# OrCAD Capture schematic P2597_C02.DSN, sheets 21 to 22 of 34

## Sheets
21 13_Gigabit Ethernet: size Custom
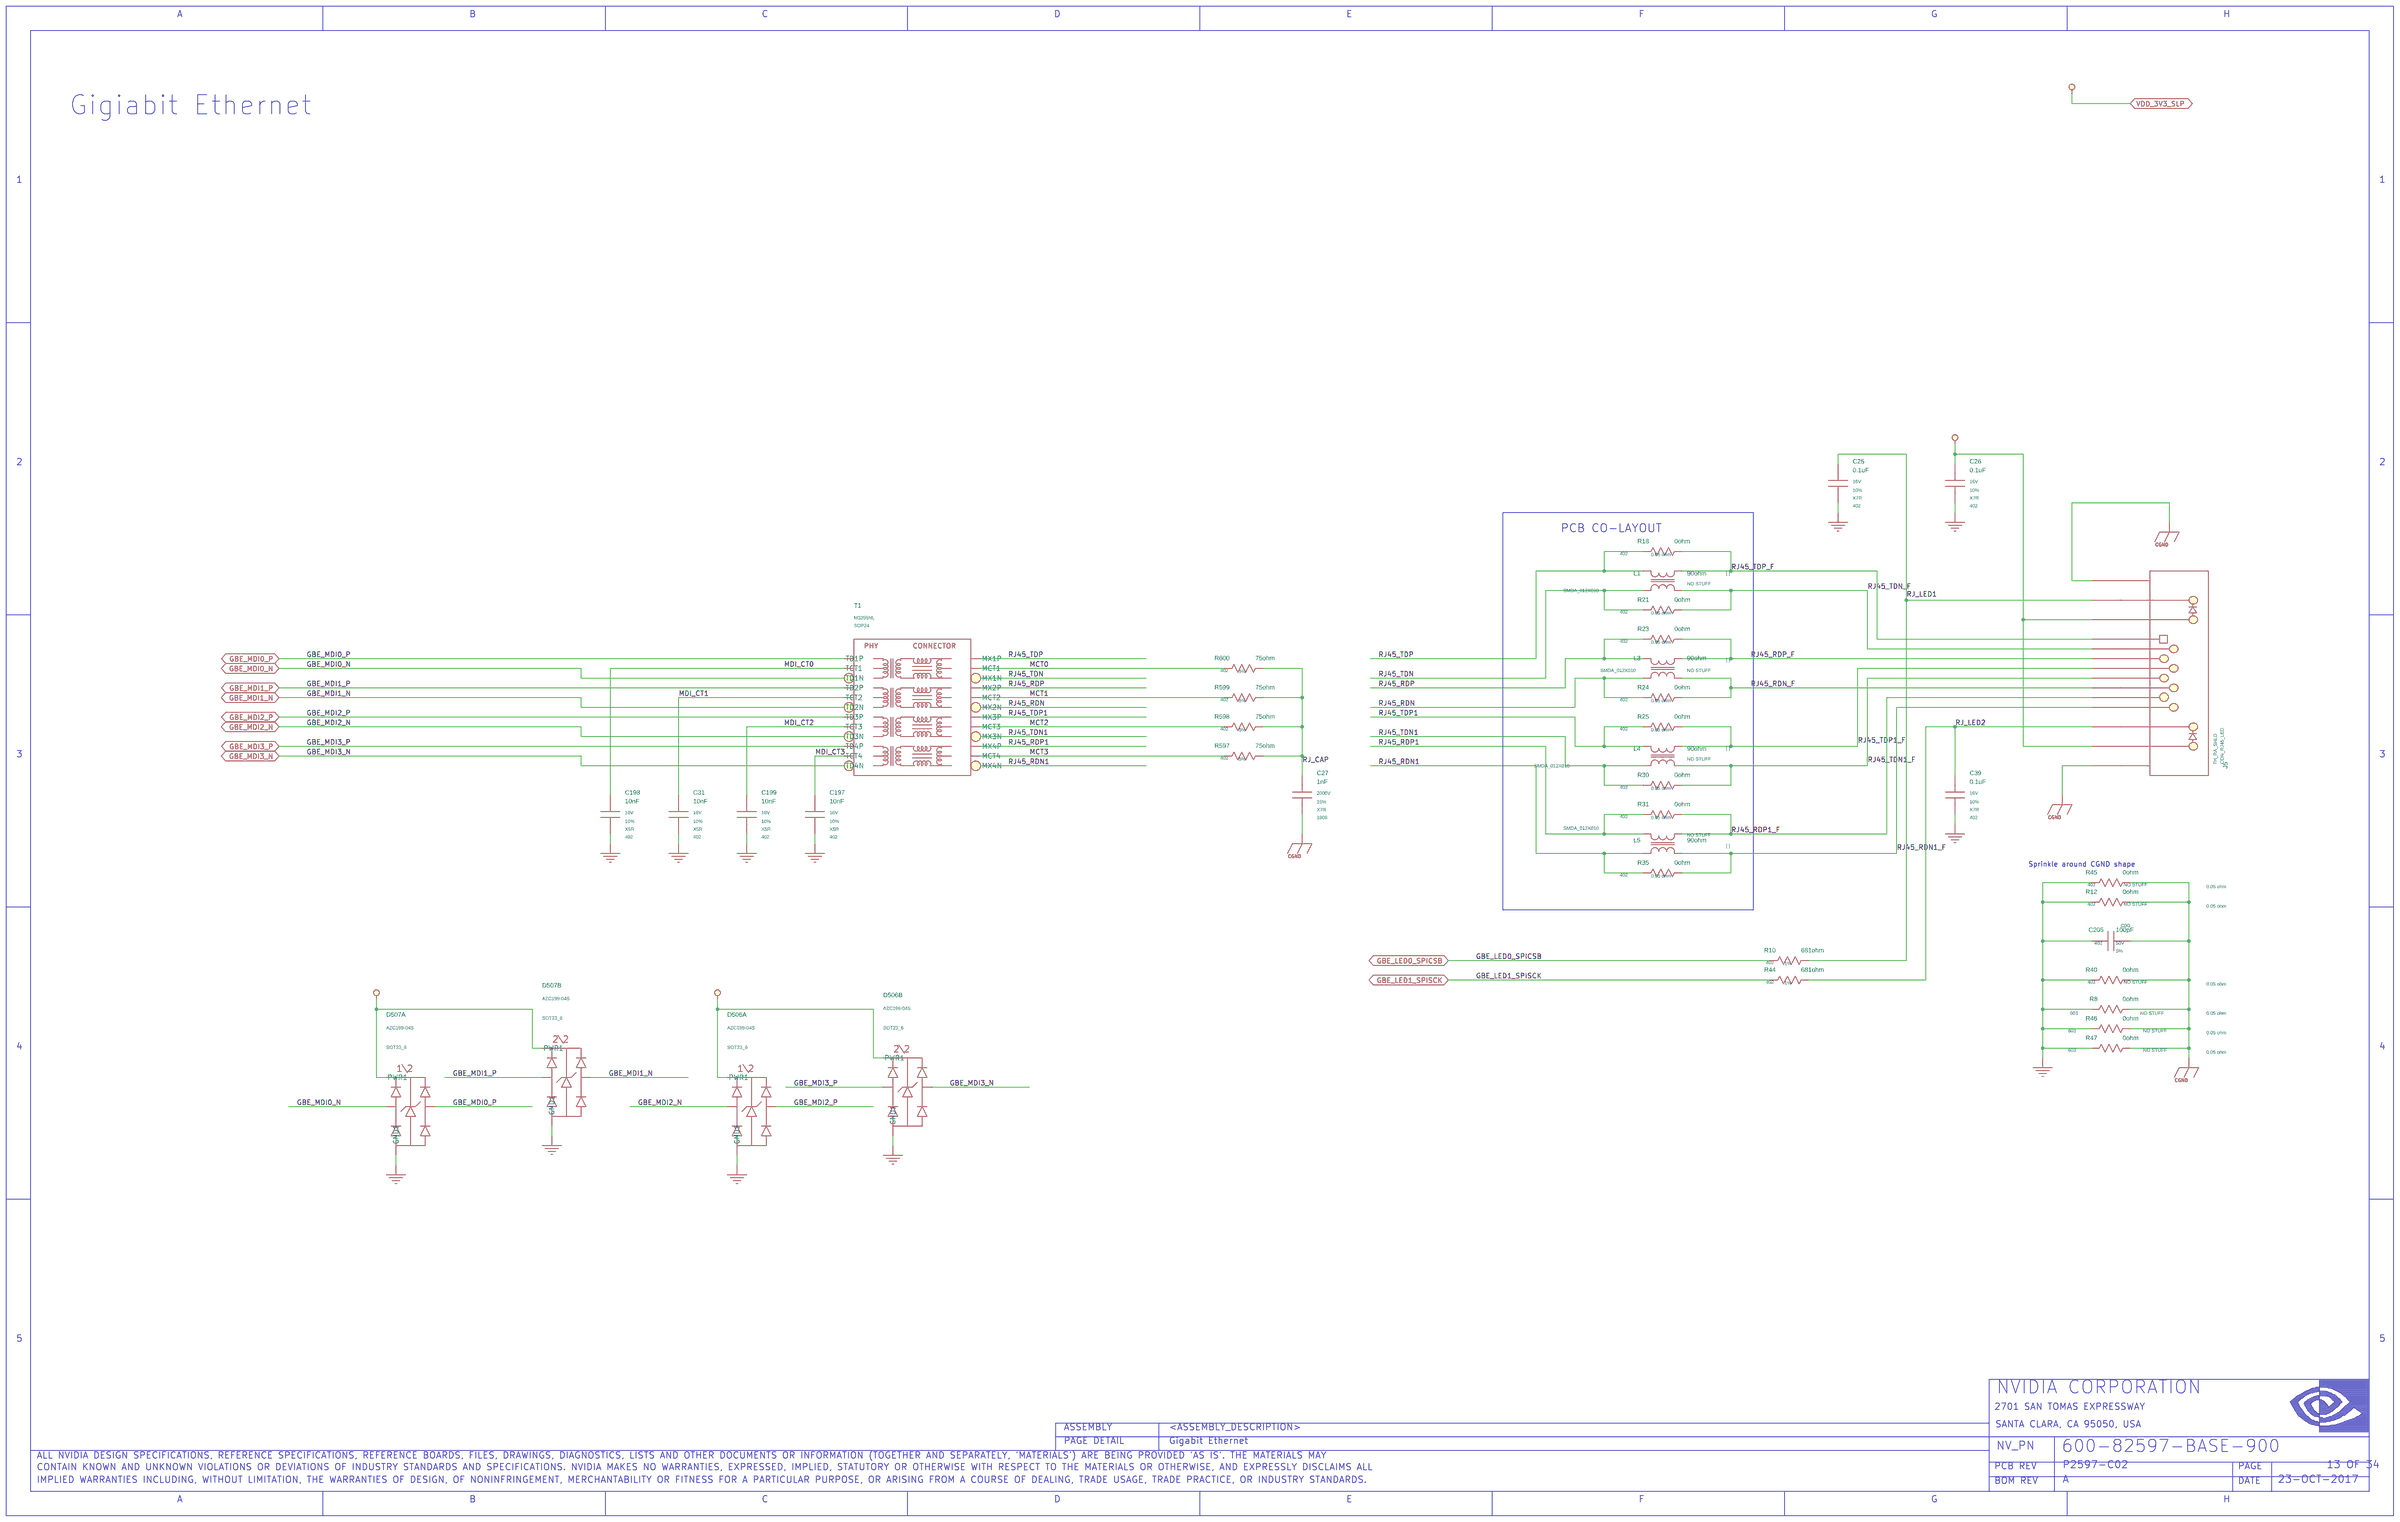
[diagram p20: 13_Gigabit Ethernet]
22 12_SATA: size Custom
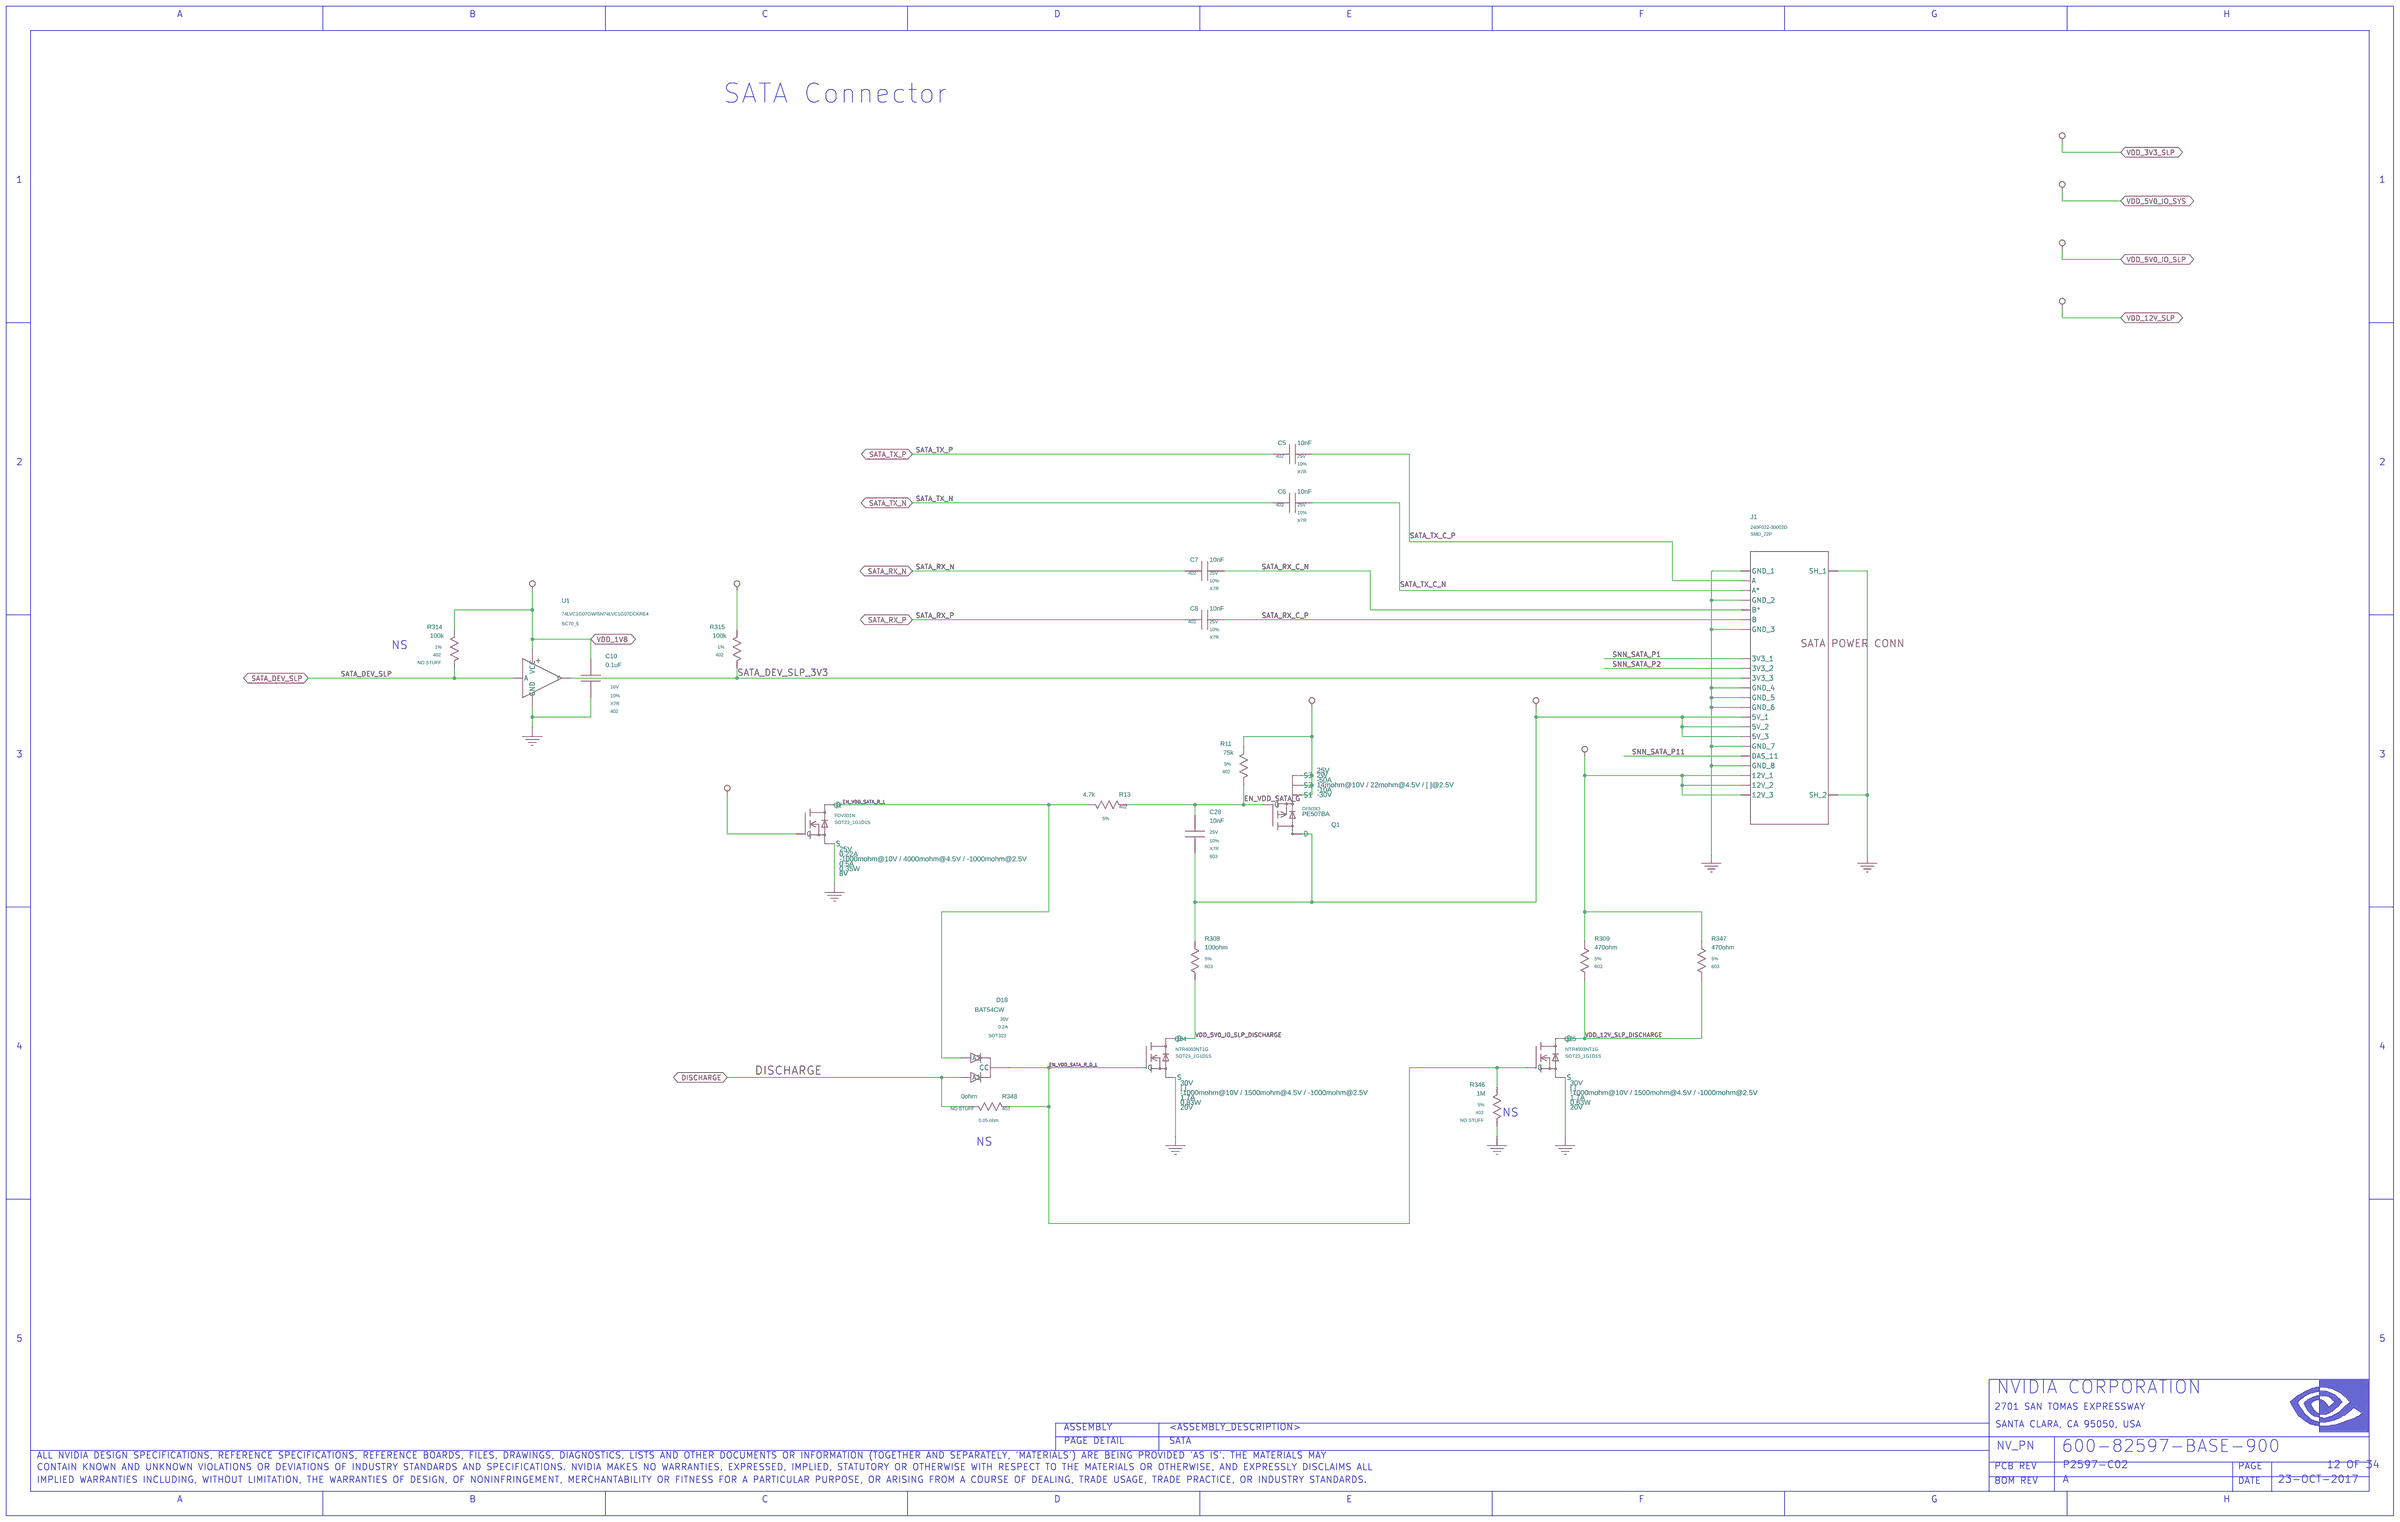
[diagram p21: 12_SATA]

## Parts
sheet 12_SATA
C5  10nF  [402]
C6  10nF  [402]
C7  10nF  [402]
C8  10nF  [402]
C10  0.1uF  [402]
C28  10nF  [603]
D18  D_3PIN_CC  [SOT323]
J1  CON_SATA  [CON_SATA_022_SMT_RA_F_P013_C]
Q1  Q_FET_P_ENH  [DFET_SMD_032X033]
Q2  Q_FET_N_ENH  [SOT23]
Q34  Q_FET_N_ENH  [SOT23]
Q35  Q_FET_N_ENH  [SOT23]
R11  75k  [402]
R13  4.7k  [402]
R308  100ohm  [603]
R309  470ohm  [603]
R314  100k  [402]
R315  100k  [402]
R346  1M  [402]
R347  470ohm  [603]
R348  0ohm  [402]
U1  U_BUF_OD  [SC70_5]
sheet 13_Gigabit Ethernet
C25  0.1uF  [402]
C26  0.1uF  [402]
C27  1nF  [4520MM]
C31  10nF  [402]
C39  0.1uF  [402]
C197  10nF  [402]
C198  10nF  [402]
C199  10nF  [402]
C205  100pF  [402]
D506  D_ESD_DIFFPAIR  [SOT23_6]  (sections A,B)
D507  D_ESD_DIFFPAIR  [SOT23_6]  (sections A,B)
J5  CON_RJ45  [CON_MJ08_012_TH_RA_2LED]
L1  90ohm  [IND_NONRKO_SMD_012X010]
L3  90ohm  [IND_NONRKO_SMD_012X010]
L4  90ohm  [IND_NONRKO_SMD_012X010]
L5  90ohm  [IND_NONRKO_SMD_012X010]
R8  0ohm  [603]
R10  681ohm  [402]
R12  0ohm  [402]
R18  0ohm  [402]
R21  0ohm  [402]
R23  0ohm  [402]
R24  0ohm  [402]
R25  0ohm  [402]
R30  0ohm  [402]
R31  0ohm  [402]
R35  0ohm  [402]
R40  0ohm  [402]
R44  681ohm  [402]
R45  0ohm  [402]
R46  0ohm  [603]
R47  0ohm  [603]
R597  75ohm  [402]
R598  75ohm  [402]
R599  75ohm  [402]
R600  75ohm  [402]
T1  1:01  [XFMR_SMD_24_151X071]

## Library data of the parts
C5 = C#1: ASSEMBLY: SATA; CDS_LIB: discrete; CDS_PART_NAME: C_0402-10NF,X7R,10%,25V,036-0019-000; CDS_PHYS_PART_NAME: C_0402-10NF,X7R,10%,25V,036-0019-000-036-0019-000,10NF; CDS_SEC: 1; CHIPS_PART_NAME: C; DEVICE_TYPENAME: C_0402-10NFX7R1025V036-0019-000-036-0019-00010NF; DRAWING: @P2597_C02_LIB.P2597_C02(SCH_1):PAGE12; MAT: X7R; MAX_VOLTAGE: 25V; NV_PN: 036-0019-000; PATH: I28; PHYS_PAGE: 12; ROT: 0; SEC: 1; SIGNAL_MODEL: nv_cap; TOL: 10%; VER: 2; XY: (-5550,5300)
C6 = C#1: ASSEMBLY: SATA; CDS_LIB: discrete; CDS_PART_NAME: C_0402-10NF,X7R,10%,25V,036-0019-000; CDS_PHYS_PART_NAME: C_0402-10NF,X7R,10%,25V,036-0019-000-036-0019-000,10NF; CDS_SEC: 1; CHIPS_PART_NAME: C; DEVICE_TYPENAME: C_0402-10NFX7R1025V036-0019-000-036-0019-00010NF; DRAWING: @P2597_C02_LIB.P2597_C02(SCH_1):PAGE12; MAT: X7R; MAX_VOLTAGE: 25V; NV_PN: 036-0019-000; PATH: I29; PHYS_PAGE: 12; ROT: 0; SEC: 1; SIGNAL_MODEL: nv_cap; TOL: 10%; VER: 2; XY: (-5550,5050)
C7 = C#1: ASSEMBLY: SATA; CDS_LIB: discrete; CDS_PART_NAME: C_0402-10NF,X7R,10%,25V,036-0019-000; CDS_PHYS_PART_NAME: C_0402-10NF,X7R,10%,25V,036-0019-000-036-0019-000,10NF; CDS_SEC: 1; CHIPS_PART_NAME: C; DEVICE_TYPENAME: C_0402-10NFX7R1025V036-0019-000-036-0019-00010NF; DRAWING: @P2597_C02_LIB.P2597_C02(SCH_1):PAGE12; MAT: X7R; MAX_VOLTAGE: 25V; NV_PN: 036-0019-000; PATH: I26; PHYS_PAGE: 12; ROT: 0; SEC: 1; SIGNAL_MODEL: nv_cap; TOL: 10%; VER: 2; XY: (-6000,4700)
C8 = C#1: ASSEMBLY: SATA; CDS_LIB: discrete; CDS_PART_NAME: C_0402-10NF,X7R,10%,25V,036-0019-000; CDS_PHYS_PART_NAME: C_0402-10NF,X7R,10%,25V,036-0019-000-036-0019-000,10NF; CDS_SEC: 1; CHIPS_PART_NAME: C; DEVICE_TYPENAME: C_0402-10NFX7R1025V036-0019-000-036-0019-00010NF; DRAWING: @P2597_C02_LIB.P2597_C02(SCH_1):PAGE12; MAT: X7R; MAX_VOLTAGE: 25V; NV_PN: 036-0019-000; PATH: I27; PHYS_PAGE: 12; ROT: 0; SEC: 1; SIGNAL_MODEL: nv_cap; TOL: 10%; VER: 2; XY: (-6000,4450)
C10 = C: ASSEMBLY: SATA; CDS_LIB: discrete; CDS_PART_NAME: C_0402-0.1UF,X7R,10%,16V,036-0014-000; CDS_PHYS_PART_NAME: C_0402-0.1UF,X7R,10%,16V,036-0014-000-0.1UF,036-0014-000; CDS_SEC: 1; DEVICE_TYPENAME: C_0402-01UFX7R1016V036-0014-000-01UF036-0014-000; DRAWING: @P2597_C02_LIB.P2597_C02(SCH_1):PAGE12; MAT: X7R; MAX_VOLTAGE: 16V; NV_PN: 036-0014-000; PATH: I54; PHYS_PAGE: 12; ROT: 0; SEC: 1; SIGNAL_MODEL: nv_cap; TOL: 10%; VER: 1; XY: (-9150,4150)
C28 = C: ASSEMBLY: SATA; CDS_LIB: discrete; CDS_PART_NAME: C_0603-10NF,X7R,10%,25V,036-0042-000; CDS_PHYS_PART_NAME: C_0603-10NF,X7R,10%,25V,036-0042-000-036-0042-000,10NF; CDS_SEC: 1; DEVICE_TYPENAME: C_0603-10NFX7R1025V036-0042-000-036-0042-00010NF; DRAWING: @P2597_C02_LIB.P2597_C02(SCH_1):PAGE12; MAT: X7R; MAX_VOLTAGE: 25V; NV_PN: 036-0042-000; PATH: I39; PHYS_PAGE: 12; ROT: 0; SEC: 1; SIGNAL_MODEL: nv_cap; TOL: 10%; VER: 1; XY: (-6050,3350)
D18 = D_3PIN_CC: ASSEMBLY: PWR_DIS; CDS_LIB: discrete; CDS_PART_NAME: D_3PIN_CC_SOT323-BAT54CW,1 PAIR - COMMON CATHODE,30V,0.6A,1V@0.1A,0.2A,091-0022-000; CDS_PHYS_PART_NAME: D_3PIN_CC_SOT323-BAT54CW,1 PAIR - COMMON CATHODE,30V,0.6A,1V@0.1A,0.2A,091-0022-000-091-0022-000; CDS_SEC: 1; CONFIGURATION: 1 Pair - Common Cathode; CONTINUOUS_CURRENT: 0.2A; DEVICE_TYPENAME: D_3PIN_CC_SOT323-BAT54CW1PAIR-COMMONCATHODE30V06A1V01A02A091-0022-000-091-0022-000; DRAWING: @P2597_C02_LIB.P2597_C02(SCH_1):PAGE12; FORWARD_VOLTAGE: 1V@0.1A; MAX_CURRENT: 0.6A; MAX_VOLTAGE: 30V; NV_NAME: BAT54CW; NV_PN: 091-0022-000; PATH: I83; PHYS_PAGE: 12; ROT: 2; SEC: 1; VER: 1; XY: (-7100,2150)
J1 = CON_SATA: ANGLE: 90; ASSEMBLY: SATA; CDS_LIB: electro_mechanic; CDS_PART_NAME: CON_SATA_SMD_22P-240F022-30002D,FEMALE,1.27MM,90,YES,N/A,YES,NO,N/A,N/A,N/A,080-0599-000; CDS_PHYS_PART_NAME: CON_SATA_SMD_22P-240F022-30002D,FEMALE,1.27MM,90,YES,N/A,YES,NO,N/A,N/A,N/A,080-0599-000-080-0599-000; CDS_SEC: 1; DEVICE_TYPENAME: CON_SATA_SMD_22P-240F022-30002DFEMALE127MM90YESNAYESNONANANA080-0599-000-080-0599-000; DRAWING: @P2597_C02_LIB.P2597_C02(SCH_1):PAGE12; EMI_GROUND_TAB: NO; GENDER: FEMALE; LATCHING: YES; MAX_CURRENT: N/A; MAX_VOLTAGE: N/A; NV_NAME: 240F022-30002D; NV_PN: 080-0599-000; PACK_TYPE: SMD_22P; PATH: I31; PHYS_PAGE: 12; PITCH: 1.27MM; REFLOW: YES; ROT: 0; SEC: 1; SEC_TYPE: SMD_22P; SHIELDED: N/A; SHROUDED: N/A; VER: 5; XY: (-3000,4100)
Q1 = Q_FET_P_ENH#1: ASSEMBLY: SATA; CDS_LIB: discrete; CDS_PART_NAME: Q_FET_P_ENH_DFN3X3-PE507BA,-30V,14MOHM@10V / 22MOHM@4.5V / [ ]@2.5V,-10A,-50A,25V,2W,49.1NC@10V / 0NC@4.5V / [ ]@2.5V,300-1028A; CDS_PHYS_PART_NAME: Q_FET_P_ENH_DFN3X3-PE507BA,-30V,14MOHM@10V / 22MOHM@4.5V / [ ]@2.5V,-10A,-50A,25V,2W,49.1NC@10V / 0NC@4.5V / [ ]@2.5V,300-1028B; CDS_SEC: 1; CONTINUOUS_CURRENT: -10A; DEVICE_TYPENAME: Q_FET_P_ENH_DFN3X3-PE507BA-30V14MOHM10V22MOHM45V25V-10A-50A25V2W491NC10V0NC45V25V300-1028B; DRAWING: @P2597_C02_LIB.P2597_C02(SCH_1):PAGE12; MAX_CURRENT: -50A; MAX_VOLTAGE: -30V; MAX_WATTAGE: 2W; NV_NAME: PE507BA; NV_PN: 300-1028-000; PACK_TYPE: DFN3X3; PATH: I40; PHYS_PAGE: 12; Q_G: 49.1nC@10V / 0nC@4.5V / [ ]@2.5V; ROT: 6; R_DS_ON: 14mohm@10V / 22mohm@4.5V / [ ]@2.5V; SEC: 1; VER: 8; V_BE_GS: 25V; XY: (-5600,3450)
Q2 = Q_FET_N_ENH#2: ASSEMBLY: DEBUG; CDS_LIB: discrete; CDS_PART_NAME: Q_FET_N_ENH_SOT23_1G1D1S-FDV301N,25V,-1000MOHM@10V / 4000MOHM@4.5V / -1000MOHM@2.5V,0.22A,0.5A,8V,0.35W,[ ]@10V / [ ]@4.5V / [A; CDS_PHYS_PART_NAME: Q_FET_N_ENH_SOT23_1G1D1S-FDV301N,25V,-1000MOHM@10V / 4000MOHM@4.5V / -1000MOHM@2.5V,0.22A,0.5A,8V,0.35W,[ ]@10V / [ ]@4.5V / [B; CDS_SEC: 1; CONTINUOUS_CURRENT: 0.22A; CaptureCellPackProp: Q_FET_N_ENH__sym_2##2; DEVICE_TYPENAME: Q_FET_N_ENH_SOT23_1G1D1S-FDV301N25V-1000MOHM10V4000MOHM45V-1000MOHM25V022A05A8V035W10V45VB; DRAWING: @P2597_C02_LIB.P2597_C02(SCH_1):PAGE12; IMPLEMENTATION_TYPE: Pspice Model; MAX_CURRENT: 0.5A; MAX_VOLTAGE: 25V; MAX_WATTAGE: 0.35W; NV_NAME: FDV301N; NV_PN: 300-0494-000; PACK_TYPE: SOT23_1G1D1S; PATH: I61; PHYS_PAGE: 12; PSPICETEMPLATE: X^@REFDES %D %G %S @NV_PN; Q_G: [ ]@10V / [ ]@4.5V / [ ]@2.5V; ROT: 0; R_DS_ON: -1000mohm@10V / 4000mohm@4.5V / -1000mohm@2.5V; SEC: 1; SEC_TYPE: SOT23_1G1D1S; VER: 2; V_BE_GS: 8V; XY: (-8000,3400)
Q34 = Q_FET_N_ENH#2: ASSEMBLY: PWR_DIS; CDS_LIB: discrete; CDS_PART_NAME: Q_FET_N_ENH_SOT23_1G1D1S-NTR4003NT1G,30V,-1000MOHM@10V / 1500MOHM@4.5V / -1000MOHM@2.5V,[ ],1.7A,20V,0.83W,[ ]@10V / [ ]@4.5V A; CDS_PHYS_PART_NAME: Q_FET_N_ENH_SOT23_1G1D1S-NTR4003NT1G,30V,-1000MOHM@10V / 1500MOHM@4.5V / -1000MOHM@2.5V,[ ],1.7A,20V,0.83W,[ ]@10V / [ ]@4.5V B; CDS_SEC: 1; CONTINUOUS_CURRENT: [ ]; CaptureCellPackProp: Q_FET_N_ENH__sym_2##2; DEVICE_TYPENAME: Q_FET_N_ENH_SOT23_1G1D1S-NTR4003NT1G30V-1000MOHM10V1500MOHM45V-1000MOHM25V17A20V083W10V45VB; DRAWING: @P2597_C02_LIB.P2597_C02(SCH_1):PAGE12; MAX_CURRENT: 1.7A; MAX_VOLTAGE: 30V; MAX_WATTAGE: 0.83W; NV_NAME: NTR4003NT1G; NV_PN: 300-0381-000; PACK_TYPE: SOT23_1G1D1S; PATH: I74; PHYS_PAGE: 12; Q_G: [ ]@10V / [ ]@4.5V / [ ]@2.5V; ROT: 0; R_DS_ON: -1000mohm@10V / 1500mohm@4.5V / -1000mohm@2.5V; SEC: 1; VER: 2; V_BE_GS: 20V; XY: (-6250,2200)
Q35 = Q_FET_N_ENH#2: ASSEMBLY: PWR_DIS; CDS_LIB: discrete; CDS_PART_NAME: Q_FET_N_ENH_SOT23_1G1D1S-NTR4003NT1G,30V,-1000MOHM@10V / 1500MOHM@4.5V / -1000MOHM@2.5V,[ ],1.7A,20V,0.83W,[ ]@10V / [ ]@4.5V A; CDS_PHYS_PART_NAME: Q_FET_N_ENH_SOT23_1G1D1S-NTR4003NT1G,30V,-1000MOHM@10V / 1500MOHM@4.5V / -1000MOHM@2.5V,[ ],1.7A,20V,0.83W,[ ]@10V / [ ]@4.5V B; CDS_SEC: 1; CONTINUOUS_CURRENT: [ ]; CaptureCellPackProp: Q_FET_N_ENH__sym_2##2; DEVICE_TYPENAME: Q_FET_N_ENH_SOT23_1G1D1S-NTR4003NT1G30V-1000MOHM10V1500MOHM45V-1000MOHM25V17A20V083W10V45VB; DRAWING: @P2597_C02_LIB.P2597_C02(SCH_1):PAGE12; MAX_CURRENT: 1.7A; MAX_VOLTAGE: 30V; MAX_WATTAGE: 0.83W; NV_NAME: NTR4003NT1G; NV_PN: 300-0381-000; PACK_TYPE: SOT23_1G1D1S; PATH: I78; PHYS_PAGE: 12; Q_G: [ ]@10V / [ ]@4.5V / [ ]@2.5V; ROT: 0; R_DS_ON: -1000mohm@10V / 1500mohm@4.5V / -1000mohm@2.5V; SEC: 1; VER: 2; V_BE_GS: 20V; XY: (-4250,2200)
R11 = R#1: ASSEMBLY: SATA; CDS_LIB: discrete; CDS_PART_NAME: R_0402-75K,5 %,62.5MW,195-0634-000; CDS_PHYS_PART_NAME: R_0402-75K,5 %,62.5MW,195-0634-000-195-0634-000,75K; CDS_SEC: 1; CHIPS_PART_NAME: R; DEVICE_TYPENAME: R_0402-75K5625MW195-0634-000-195-0634-00075K; DRAWING: @P2597_C02_LIB.P2597_C02(SCH_1):PAGE12; MAX_WATTAGE: 62.5mW; NV_PN: 195-0634-000; PATH: I41; PHYS_PAGE: 12; ROT: 2; SEC: 1; SIGNAL_MODEL: nv_res; TOL: 5%; VER: 2; XY: (-5800,3700)
R13 = R: ASSEMBLY: SATA; CDS_LIB: discrete; CDS_PART_NAME: R_0402-4.7K,5 %,62.5MW,195-0598-000; CDS_PHYS_PART_NAME: R_0402-4.7K,5 %,62.5MW,195-0598-000-195-0598-000,4.7K; CDS_SEC: 1; DEVICE_TYPENAME: R_0402-47K5625MW195-0598-000-195-0598-00047K; DRAWING: @P2597_C02_LIB.P2597_C02(SCH_1):PAGE12; MAX_WATTAGE: 62.5mW; NV_PN: 195-0598-000; PATH: I38; PHYS_PAGE: 12; ROT: 2; SEC: 1; SIGNAL_MODEL: nv_res; TOL: 5%; VER: 1; XY: (-6500,3500)
R308 = R#1: ASSEMBLY: PWR_DIS; CDS_LIB: discrete; CDS_PART_NAME: R_0603-100OHM,5 %,0.1W,195-1134-000; CDS_PHYS_PART_NAME: R_0603-100OHM,5 %,0.1W,195-1134-000-100OHM,195-1134-000; CDS_SEC: 1; CHIPS_PART_NAME: R; DEVICE_TYPENAME: R_0603-100OHM501W195-1134-000-100OHM195-1134-000; DRAWING: @P2597_C02_LIB.P2597_C02(SCH_1):PAGE12; MAX_WATTAGE: 0.1W; NV_PN: 195-1134-000; PATH: I75; PHYS_PAGE: 12; ROT: 0; SEC: 1; SIGNAL_MODEL: nv_res; TOL: 5%; VER: 2; XY: (-6050,2700)
R309 = R#1: ASSEMBLY: PWR_DIS; CDS_LIB: discrete; CDS_PART_NAME: R_0603-470OHM,5 %,0.1W,195-1247-000; CDS_PHYS_PART_NAME: R_0603-470OHM,5 %,0.1W,195-1247-000-195-1247-000,470OHM; CDS_SEC: 1; CHIPS_PART_NAME: R; DEVICE_TYPENAME: R_0603-470OHM501W195-1247-000-195-1247-000470OHM; DRAWING: @P2597_C02_LIB.P2597_C02(SCH_1):PAGE12; MAX_WATTAGE: 0.1W; NV_PN: 195-1247-000; PATH: I79; PHYS_PAGE: 12; ROT: 0; SEC: 1; SIGNAL_MODEL: nv_res; TOL: 5%; VER: 2; XY: (-4050,2700)
R314 = R#1: ASSEMBLY: SATA; CDS_LIB: discrete; CDS_PART_NAME: R_0402-100K,1 %,62.5MW,195-0005-000; CDS_PHYS_PART_NAME: R_0402-100K,1 %,62.5MW,195-0005-000-100K,195-0005-000; CDS_SEC: 1; CHIPS_PART_NAME: R; DEVICE_TYPENAME: R_0402-100K1625MW195-0005-000-100K195-0005-000; DRAWING: @P2597_C02_LIB.P2597_C02(SCH_1):PAGE12; MAX_WATTAGE: 62.5mW; NV_PN: 195-0005-000; PATH: I82; PHYS_PAGE: 12; ROT: 2; SEC: 1; SIGNAL_MODEL: nv_res; SKU: NO STUFF; TOL: 1%; VER: 2; XY: (-9850,4300)
R315 = R#1: ASSEMBLY: SATA; CDS_LIB: discrete; CDS_PART_NAME: R_0402-100K,1 %,62.5MW,195-0005-000; CDS_PHYS_PART_NAME: R_0402-100K,1 %,62.5MW,195-0005-000-100K,195-0005-000; CDS_SEC: 1; CHIPS_PART_NAME: R; DEVICE_TYPENAME: R_0402-100K1625MW195-0005-000-100K195-0005-000; DRAWING: @P2597_C02_LIB.P2597_C02(SCH_1):PAGE12; MAX_WATTAGE: 62.5mW; NV_PN: 195-0005-000; PATH: I81; PHYS_PAGE: 12; ROT: 2; SEC: 1; SIGNAL_MODEL: nv_res; TOL: 1%; VER: 2; XY: (-8400,4300)
R346 = R#1: ASSEMBLY: PWR_DIS; CDS_LIB: discrete; CDS_PART_NAME: R_0402-1M,5 %,62.5MW,195-0488-000; CDS_PHYS_PART_NAME: R_0402-1M,5 %,62.5MW,195-0488-000-195-0488-000,1M; CDS_SEC: 1; CHIPS_PART_NAME: R; DEVICE_TYPENAME: R_0402-1M5625MW195-0488-000-195-0488-0001M; DRAWING: @P2597_C02_LIB.P2597_C02(SCH_1):PAGE12; MAX_WATTAGE: 62.5mW; NV_PN: 195-0488-000; PATH: I85; PHYS_PAGE: 12; ROT: 2; SEC: 1; SIGNAL_MODEL: nv_res; SKU: NO STUFF; TOL: 5%; VER: 2; XY: (-4500,1950)
R347 = R#1: ASSEMBLY: PWR_DIS; CDS_LIB: discrete; CDS_PART_NAME: R_0603-470OHM,5 %,0.1W,195-1247-000; CDS_PHYS_PART_NAME: R_0603-470OHM,5 %,0.1W,195-1247-000-195-1247-000,470OHM; CDS_SEC: 1; CHIPS_PART_NAME: R; DEVICE_TYPENAME: R_0603-470OHM501W195-1247-000-195-1247-000470OHM; DRAWING: @P2597_C02_LIB.P2597_C02(SCH_1):PAGE12; MAX_WATTAGE: 0.1W; NV_PN: 195-1247-000; PATH: I87; PHYS_PAGE: 12; ROT: 0; SEC: 1; SIGNAL_MODEL: nv_res; TOL: 5%; VER: 2; XY: (-3450,2700)
R348 = R: ASSEMBLY: PWR_DIS; CDS_LIB: discrete; CDS_PART_NAME: R_0402-0OHM,0.05 OHM,62.5MW,195-2655-000; CDS_PHYS_PART_NAME: R_0402-0OHM,0.05 OHM,62.5MW,195-2655-000-0OHM,195-2655-000; CDS_SEC: 1; DEVICE_TYPENAME: R_0402-0OHM005OHM625MW195-2655-000-0OHM195-2655-000; DRAWING: @P2597_C02_LIB.P2597_C02(SCH_1):PAGE12; MAX_WATTAGE: 62.5mW; NV_PN: 195-2655-000; PATH: I88; PHYS_PAGE: 12; ROT: 2; SEC: 1; SIGNAL_MODEL: nv_res; SKU: NO STUFF; TOL: 0.05 ohm; VER: 1; XY: (-7100,1950)
U1 = U_BUF_OD#1: ASSEMBLY: SATA; CDS_LIB: logic; CDS_PART_NAME: U_BUF_OD_SC70_5-74LVC1G07GW/SN74LVC1G07DCKRE4,BUFFER - OPEN DRAIN,115-0138-000; CDS_PHYS_PART_NAME: U_BUF_OD_SC70_5-74LVC1G07GW/SN74LVC1G07DCKRE4,BUFFER - OPEN DRAIN,115-0138-000-115-0138-000; CDS_SEC: 1; CaptureCellPackProp: U_BUF_OD##1; DEVICE_TYPENAME: U_BUF_OD_SC70_5-74LVC1G07GWSN74LVC1G07DCKRE4BUFFER-OPENDRAIN115-0138-000-115-0138-000; DRAWING: @P2597_C02_LIB.P2597_C02(SCH_1):PAGE12; FUNCTION: Buffer - Open Drain; NC: 1; NV_NAME: 74LVC1G07GW/SN74LVC1G07DCKRE4; NV_PN: 115-0138-000; PATH: I80; PHYS_PAGE: 12; ROT: 0; SEC: 1; VER: 1; XY: (-9400,4150)
C25 = C: ASSEMBLY: ETHERNET; CDS_LIB: discrete; CDS_PART_NAME: C_0402-0.1UF,X7R,10%,16V,036-0014-000; CDS_PHYS_PART_NAME: C_0402-0.1UF,X7R,10%,16V,036-0014-000-0.1UF,036-0014-000; CDS_SEC: 1; DEVICE_TYPENAME: C_0402-01UFX7R1016V036-0014-000-01UF036-0014-000; DRAWING: @P2597_C02_LIB.P2597_C02(SCH_1):PAGE13; ESL: N/A; ESR: N/A; MAT: X7R; MAX_VOLTAGE: 16V; NV_PN: 036-0014-000; PATH: I340; PHYS_PAGE: 13; ROT: 0; SEC: 1; SIGNAL_MODEL: nv_cap; TOL: 10%; VER: 1; XY: (-2750,5150)
C26 = C: ASSEMBLY: ETHERNET; CDS_LIB: discrete; CDS_PART_NAME: C_0402-0.1UF,X7R,10%,16V,036-0014-000; CDS_PHYS_PART_NAME: C_0402-0.1UF,X7R,10%,16V,036-0014-000-0.1UF,036-0014-000; CDS_SEC: 1; DEVICE_TYPENAME: C_0402-01UFX7R1016V036-0014-000-01UF036-0014-000; DRAWING: @P2597_C02_LIB.P2597_C02(SCH_1):PAGE13; ESL: N/A; ESR: N/A; MAT: X7R; MAX_VOLTAGE: 16V; NV_PN: 036-0014-000; PATH: I342; PHYS_PAGE: 13; ROT: 0; SEC: 1; SIGNAL_MODEL: nv_cap; TOL: 10%; VER: 1; XY: (-2150,5150)
C27 = C: ASSEMBLY: ETHERNET; CDS_LIB: discrete; CDS_PART_NAME: C_1808-1NF,X7R,15%,2000V,032-0166-000; CDS_PHYS_PART_NAME: C_1808-1NF,X7R,15%,2000V,032-0166-000-032-0166-000,1NF; CDS_SEC: 1; DEVICE_TYPENAME: C_1808-1NFX7R152000V032-0166-000-032-0166-0001NF; DRAWING: @P2597_C02_LIB.P2597_C02(SCH_1):PAGE13; MAT: X7R; MAX_VOLTAGE: 2000V; NV_PN: 032-0166-000; PACK_TYPE: 1808; PATH: I293; PHYS_PAGE: 13; ROT: 0; SEC: 1; SIGNAL_MODEL: DEFAULT_CAPACITOR_1000pF_2_1; TOL: 15%; VER: 1; XY: (-5500,3550)
C31 = C: ASSEMBLY: ETHERNET; CDS_LIB: discrete; CDS_PART_NAME: C_0402-10NF,X5R,10%,16V,039-0024-000; CDS_PHYS_PART_NAME: C_0402-10NF,X5R,10%,16V,039-0024-000-039-0024-000,10NF; CDS_SEC: 1; DEVICE_TYPENAME: C_0402-10NFX5R1016V039-0024-000-039-0024-00010NF; DRAWING: @P2597_C02_LIB.P2597_C02(SCH_1):PAGE13; MAT: X5R; MAX_VOLTAGE: 16V; NV_PN: 039-0024-000; PATH: I419; PHYS_PAGE: 13; ROT: 0; SEC: 1; SIGNAL_MODEL: DEFAULT_CAPACITOR_10000pF_2_1; TOL: 10%; VER: 1; XY: (-8700,3450)
C39 = C: ASSEMBLY: ETHERNET; CDS_LIB: discrete; CDS_PART_NAME: C_0402-0.1UF,X7R,10%,16V,036-0014-000; CDS_PHYS_PART_NAME: C_0402-0.1UF,X7R,10%,16V,036-0014-000-0.1UF,036-0014-000; CDS_SEC: 1; DEVICE_TYPENAME: C_0402-01UFX7R1016V036-0014-000-01UF036-0014-000; DRAWING: @P2597_C02_LIB.P2597_C02(SCH_1):PAGE13; ESL: N/A; ESR: N/A; MAT: X7R; MAX_VOLTAGE: 16V; NV_PN: 036-0014-000; PATH: I338; PHYS_PAGE: 13; ROT: 0; SEC: 1; SIGNAL_MODEL: nv_cap; TOL: 10%; VER: 1; XY: (-2150,3550)
C197 = C: ASSEMBLY: ETHERNET; CDS_LIB: discrete; CDS_PART_NAME: C_0402-10NF,X5R,10%,16V,039-0024-000; CDS_PHYS_PART_NAME: C_0402-10NF,X5R,10%,16V,039-0024-000-039-0024-000,10NF; CDS_SEC: 1; DEVICE_TYPENAME: C_0402-10NFX5R1016V039-0024-000-039-0024-00010NF; DRAWING: @P2597_C02_LIB.P2597_C02(SCH_1):PAGE13; MAT: X5R; MAX_VOLTAGE: 16V; NV_PN: 039-0024-000; PATH: I291; PHYS_PAGE: 13; ROT: 0; SEC: 1; SIGNAL_MODEL: DEFAULT_CAPACITOR_10000pF_2_1; TOL: 10%; VER: 1; XY: (-8000,3450)
C198 = C: ASSEMBLY: ETHERNET; CDS_LIB: discrete; CDS_PART_NAME: C_0402-10NF,X5R,10%,16V,039-0024-000; CDS_PHYS_PART_NAME: C_0402-10NF,X5R,10%,16V,039-0024-000-039-0024-000,10NF; CDS_SEC: 1; DEVICE_TYPENAME: C_0402-10NFX5R1016V039-0024-000-039-0024-00010NF; DRAWING: @P2597_C02_LIB.P2597_C02(SCH_1):PAGE13; MAT: X5R; MAX_VOLTAGE: 16V; NV_PN: 039-0024-000; PATH: I421; PHYS_PAGE: 13; ROT: 0; SEC: 1; SIGNAL_MODEL: DEFAULT_CAPACITOR_10000pF_2_1; TOL: 10%; VER: 1; XY: (-9050,3450)
C199 = C: ASSEMBLY: ETHERNET; CDS_LIB: discrete; CDS_PART_NAME: C_0402-10NF,X5R,10%,16V,039-0024-000; CDS_PHYS_PART_NAME: C_0402-10NF,X5R,10%,16V,039-0024-000-039-0024-000,10NF; CDS_SEC: 1; DEVICE_TYPENAME: C_0402-10NFX5R1016V039-0024-000-039-0024-00010NF; DRAWING: @P2597_C02_LIB.P2597_C02(SCH_1):PAGE13; MAT: X5R; MAX_VOLTAGE: 16V; NV_PN: 039-0024-000; PATH: I417; PHYS_PAGE: 13; ROT: 0; SEC: 1; SIGNAL_MODEL: DEFAULT_CAPACITOR_10000pF_2_1; TOL: 10%; VER: 1; XY: (-8350,3450)
C205 = C#1: ASSEMBLY: ETHERNET; CDS_LIB: discrete; CDS_PART_NAME: C_0402-100PF,C0G,5%,50V,035-0012-000; CDS_PHYS_PART_NAME: C_0402-100PF,C0G,5%,50V,035-0012-000-035-0012-000,100PF; CDS_SEC: 1; CHIPS_PART_NAME: C; DEVICE_TYPENAME: C_0402-100PFC0G550V035-0012-000-035-0012-000100PF; DRAWING: @P2597_C02_LIB.P2597_C02(SCH_1):PAGE13; ESL: N/A; ESR: N/A; MAT: C0G; MAX_VOLTAGE: 50V; NV_PN: 035-0012-000; PATH: I416; PHYS_PAGE: 13; ROT: 0; SEC: 1; SIGNAL_MODEL: nv_cap; TOL: 5%; VER: 2; XY: (-1350,2800)
D506 = D_ESD_DIFFPAIR: ASSEMBLY: ETHERNET; BREAKDOWN_VOLTAGE_MIN_TYP: 6V; CAPACITANCE_MAX_TYP: 1.7pF; CDS_LIB: discrete; CDS_PART_NAME: D_ESD_DIFFPAIR_SOT23_6-AZC199-04S,2 DIFFPAIR,UNI-DIRECTIONAL,5V,1UA,6V,11V@6A,1.7PF,091-0053-000; CDS_PHYS_PART_NAME: D_ESD_DIFFPAIR_SOT23_6-AZC199-04S,2 DIFFPAIR,UNI-DIRECTIONAL,5V,1UA,6V,11V@6A,1.7PF,091-0053-000-091-0053-000; CDS_SEC: 1; CLAMPING_VOLTAGE: 11V@6A; CONFIGURATION: 2 Diffpair; CaptureCellPackProp: D_ESD_DIFFPAIRA; DEVICE_TYPENAME: D_ESD_DIFFPAIR_SOT23_6-AZC199-04S2DIFFPAIRUNI-DIRECTIONAL5V1UA6V11V6A17PF091-0053-000-091-0053-000; DRAWING: @P2597_C02_LIB.P2597_C02(SCH_1):PAGE13; MAX_REVERSE_LEAKAGE_CURRENT: 1uA; MAX_REVERSE_VOLTAGE: 5V; NV_NAME: AZC199-04S; NV_PN: 091-0053-000; PATH: I347; PHYS_PAGE: 13; POLARITY: Uni-Directional; ROT: 0; SEC: 1; VER: 4; XY: (-8350,1950)
D507 = D_ESD_DIFFPAIR: ASSEMBLY: ETHERNET; BREAKDOWN_VOLTAGE_MIN_TYP: 6V; CAPACITANCE_MAX_TYP: 1.7pF; CDS_LIB: discrete; CDS_PART_NAME: D_ESD_DIFFPAIR_SOT23_6-AZC199-04S,2 DIFFPAIR,UNI-DIRECTIONAL,5V,1UA,6V,11V@6A,1.7PF,091-0053-000; CDS_PHYS_PART_NAME: D_ESD_DIFFPAIR_SOT23_6-AZC199-04S,2 DIFFPAIR,UNI-DIRECTIONAL,5V,1UA,6V,11V@6A,1.7PF,091-0053-000-091-0053-000; CDS_SEC: 1; CLAMPING_VOLTAGE: 11V@6A; CONFIGURATION: 2 Diffpair; CaptureCellPackProp: D_ESD_DIFFPAIRA; DEVICE_TYPENAME: D_ESD_DIFFPAIR_SOT23_6-AZC199-04S2DIFFPAIRUNI-DIRECTIONAL5V1UA6V11V6A17PF091-0053-000-091-0053-000; DRAWING: @P2597_C02_LIB.P2597_C02(SCH_1):PAGE13; MAX_REVERSE_LEAKAGE_CURRENT: 1uA; MAX_REVERSE_VOLTAGE: 5V; NV_NAME: AZC199-04S; NV_PN: 091-0053-000; PATH: I310; PHYS_PAGE: 13; POLARITY: Uni-Directional; ROT: 0; SEC: 1; VER: 4; XY: (-10100,1950)
J5 = CON_RJ45: ANGLE: 90; ASSEMBLY: ETHERNET; CDS_LIB: electro_mechanic; CDS_PART_NAME: CON_RJ45_TH_RA_SHLD-CON_RJ45_LED,FEMALE,40MIL,90,NO,YES,YES,YES,YES,N/A,N/A,065-0014-000; CDS_PHYS_PART_NAME: CON_RJ45_TH_RA_SHLD-CON_RJ45_LED,FEMALE,40MIL,90,NO,YES,YES,YES,YES,N/A,N/A,065-0014-000-065-0014-000; CDS_SEC: 1; DEVICE_TYPENAME: CON_RJ45_TH_RA_SHLD-CON_RJ45_LEDFEMALE40MIL90NOYESYESYESYESNANA065-0014-000-065-0014-000; DRAWING: @P2597_C02_LIB.P2597_C02(SCH_1):PAGE13; EMI_GROUND_TAB: YES; GENDER: FEMALE; LATCHING: YES; MAX_CURRENT: N/A; MAX_VOLTAGE: N/A; NV_NAME: CON_RJ45_LED; NV_PN: 065-0014-000; PACK_TYPE: TH_RA_SHLD; PATH: I374; PHYS_PAGE: 13; PITCH: 40MIL; REFLOW: NO; ROT: 7; SEC: 1; SEC_TYPE: TH_RA_SHLD; SHIELDED: YES; SHROUDED: YES; VER: 1; XY: (-1000,4150)
L1 = L_CMF_4P: ASSEMBLY: ETHERNET; CDS_LIB: discrete; CDS_PART_NAME: L_CMF_4P_SMDA_012X010-90OHM,[ ],25%,0.2A,0.4OHM,[ ],102-0037-000; CDS_PHYS_PART_NAME: L_CMF_4P_SMDA_012X010-90OHM,[ ],25%,0.2A,0.4OHM,[ ],102-0037-000-102-0037-000,90OHM; CDS_SEC: 1; DC_RESISTANCE: 0.4ohm; DEVICE_TYPENAME: L_CMF_4P_SMDA_012X010-90OHM2502A04OHM102-0037-000-102-0037-00090OHM; DRAWING: @P2597_C02_LIB.P2597_C02(SCH_1):PAGE13; MAT: [ ]; MAX_CURRENT: 0.2A; NV_NAME: [ ]; NV_PN: 102-0037-000; PACK_TYPE: SMDA_012X010; PATH: I332; PHYS_PAGE: 13; PLACEMENT_NOTE: CoLayout with R18, R21; ROT: 0; SEC: 1; SEC_TYPE: SMDA_012X010; SIGNAL_MODEL: nv_ind_cmf_4p; SKU: NO STUFF; TOL: 25%; VER: 1; XY: (-3650,4650)
L3 = L_CMF_4P: ASSEMBLY: ETHERNET; CDS_LIB: discrete; CDS_PART_NAME: L_CMF_4P_SMDA_012X010-90OHM,[ ],25%,0.2A,0.4OHM,[ ],102-0037-000; CDS_PHYS_PART_NAME: L_CMF_4P_SMDA_012X010-90OHM,[ ],25%,0.2A,0.4OHM,[ ],102-0037-000-102-0037-000,90OHM; CDS_SEC: 1; DC_RESISTANCE: 0.4ohm; DEVICE_TYPENAME: L_CMF_4P_SMDA_012X010-90OHM2502A04OHM102-0037-000-102-0037-00090OHM; DRAWING: @P2597_C02_LIB.P2597_C02(SCH_1):PAGE13; MAT: [ ]; MAX_CURRENT: 0.2A; NV_NAME: [ ]; NV_PN: 102-0037-000; PACK_TYPE: SMDA_012X010; PATH: I329; PHYS_PAGE: 13; PLACEMENT_NOTE: CoLayout with R23, R24; ROT: 0; SEC: 1; SEC_TYPE: SMDA_012X010; SIGNAL_MODEL: nv_ind_cmf_4p; SKU: NO STUFF; TOL: 25%; VER: 1; XY: (-3650,4200)
L4 = L_CMF_4P: ASSEMBLY: ETHERNET; CDS_LIB: discrete; CDS_PART_NAME: L_CMF_4P_SMDA_012X010-90OHM,[ ],25%,0.2A,0.4OHM,[ ],102-0037-000; CDS_PHYS_PART_NAME: L_CMF_4P_SMDA_012X010-90OHM,[ ],25%,0.2A,0.4OHM,[ ],102-0037-000-102-0037-000,90OHM; CDS_SEC: 1; DC_RESISTANCE: 0.4ohm; DEVICE_TYPENAME: L_CMF_4P_SMDA_012X010-90OHM2502A04OHM102-0037-000-102-0037-00090OHM; DRAWING: @P2597_C02_LIB.P2597_C02(SCH_1):PAGE13; MAT: [ ]; MAX_CURRENT: 0.2A; NV_NAME: [ ]; NV_PN: 102-0037-000; PACK_TYPE: SMDA_012X010; PATH: I326; PHYS_PAGE: 13; PLACEMENT_NOTE: CoLayout with R25, R30; ROT: 0; SEC: 1; SEC_TYPE: SMDA_012X010; SIGNAL_MODEL: nv_ind_cmf_4p; SKU: NO STUFF; TOL: 25%; VER: 1; XY: (-3650,3750)
L5 = L_CMF_4P#2: ASSEMBLY: ETHERNET; CDS_LIB: discrete; CDS_PART_NAME: L_CMF_4P_SMDA_012X010-90OHM,[ ],25%,0.2A,0.4OHM,[ ],102-0037-000; CDS_PHYS_PART_NAME: L_CMF_4P_SMDA_012X010-90OHM,[ ],25%,0.2A,0.4OHM,[ ],102-0037-000-102-0037-000,90OHM; CDS_SEC: 1; CHIPS_PART_NAME: L_CMF_4P; DC_RESISTANCE: 0.4ohm; DEVICE_TYPENAME: L_CMF_4P_SMDA_012X010-90OHM2502A04OHM102-0037-000-102-0037-00090OHM; DRAWING: @P2597_C02_LIB.P2597_C02(SCH_1):PAGE13; MAT: [ ]; MAX_CURRENT: 0.2A; NV_NAME: [ ]; NV_PN: 102-0037-000; PACK_TYPE: SMDA_012X010; PATH: I385; PHYS_PAGE: 13; PLACEMENT_NOTE: CoLayout with R31, R35; ROT: 6; SEC: 1; SEC_TYPE: SMDA_012X010; SIGNAL_MODEL: nv_ind_cmf_4p; SKU: NO STUFF; TOL: 25%; VER: 3; XY: (-3650,3300)
R8 = R: ASSEMBLY: ETHERNET; CDS_LIB: discrete; CDS_PART_NAME: R_0603-0OHM,0.05 OHM,0.1W,195-2656-000; CDS_PHYS_PART_NAME: R_0603-0OHM,0.05 OHM,0.1W,195-2656-000-0OHM,195-2656-000; CDS_SEC: 1; DEVICE_TYPENAME: R_0603-0OHM005OHM01W195-2656-000-0OHM195-2656-000; DRAWING: @P2597_C02_LIB.P2597_C02(SCH_1):PAGE13; MAX_WATTAGE: 0.1W; NV_PN: 195-2656-000; PATH: I345; PHYS_PAGE: 13; ROT: 0; SEC: 1; SIGNAL_MODEL: DEFAULT_RESISTOR_0.001OHM_2_1; SKU: NO STUFF; TOL: 0.05 ohm; VER: 1; XY: (-1350,2450)
R10 = R: ASSEMBLY: ETHERNET; CDS_LIB: discrete; CDS_PART_NAME: R_0402-681OHM,1 %,62.5MW,195-0403-000; CDS_PHYS_PART_NAME: R_0402-681OHM,1 %,62.5MW,195-0403-000-195-0403-000,681OHM; CDS_SEC: 1; DEVICE_TYPENAME: R_0402-681OHM1625MW195-0403-000-195-0403-000681OHM; DRAWING: @P2597_C02_LIB.P2597_C02(SCH_1):PAGE13; MAX_WATTAGE: 62.5mW; NV_PN: 195-0403-000; PATH: I320; PHYS_PAGE: 13; ROT: 0; SEC: 1; SIGNAL_MODEL: DEFAULT_RESISTOR_510OHM_2_1; TOL: 1%; VER: 1; XY: (-3000,2700)
R12 = R: ASSEMBLY: ETHERNET; CDS_LIB: discrete; CDS_PART_NAME: R_0402-0OHM,0.05 OHM,62.5MW,195-2655-000; CDS_PHYS_PART_NAME: R_0402-0OHM,0.05 OHM,62.5MW,195-2655-000-0OHM,195-2655-000; CDS_SEC: 1; DEVICE_TYPENAME: R_0402-0OHM005OHM625MW195-2655-000-0OHM195-2655-000; DRAWING: @P2597_C02_LIB.P2597_C02(SCH_1):PAGE13; MAX_WATTAGE: 62.5mW; NV_PN: 195-2655-000; PATH: I392; PHYS_PAGE: 13; ROT: 0; SEC: 1; SIGNAL_MODEL: nv_res; SKU: NO STUFF; TOL: 0.05 ohm; VER: 1; XY: (-1350,3000)
R18 = R: ASSEMBLY: ETHERNET; CDS_LIB: discrete; CDS_PART_NAME: R_0402-0OHM,0.05 OHM,62.5MW,195-2655-000; CDS_PHYS_PART_NAME: R_0402-0OHM,0.05 OHM,62.5MW,195-2655-000-0OHM,195-2655-000; CDS_SEC: 1; DEVICE_TYPENAME: R_0402-0OHM005OHM625MW195-2655-000-0OHM195-2655-000; DRAWING: @P2597_C02_LIB.P2597_C02(SCH_1):PAGE13; MAX_WATTAGE: 62.5mW; NV_PN: 195-2655-000; PATH: I333; PHYS_PAGE: 13; PLACEMENT_NOTE: CoLayout with L1; ROT: 0; SEC: 1; SIGNAL_MODEL: DEFAULT_RESISTOR_0.001OHM_2_1; TOL: 0.05 ohm; VER: 1; XY: (-3650,4800)
R21 = R: ASSEMBLY: ETHERNET; CDS_LIB: discrete; CDS_PART_NAME: R_0402-0OHM,0.05 OHM,62.5MW,195-2655-000; CDS_PHYS_PART_NAME: R_0402-0OHM,0.05 OHM,62.5MW,195-2655-000-0OHM,195-2655-000; CDS_SEC: 1; DEVICE_TYPENAME: R_0402-0OHM005OHM625MW195-2655-000-0OHM195-2655-000; DRAWING: @P2597_C02_LIB.P2597_C02(SCH_1):PAGE13; MAX_WATTAGE: 62.5mW; NV_PN: 195-2655-000; PATH: I331; PHYS_PAGE: 13; PLACEMENT_NOTE: CoLayout with L1; ROT: 0; SEC: 1; SIGNAL_MODEL: DEFAULT_RESISTOR_0.001OHM_2_1; TOL: 0.05 ohm; VER: 1; XY: (-3650,4500)
R23 = R: ASSEMBLY: ETHERNET; CDS_LIB: discrete; CDS_PART_NAME: R_0402-0OHM,0.05 OHM,62.5MW,195-2655-000; CDS_PHYS_PART_NAME: R_0402-0OHM,0.05 OHM,62.5MW,195-2655-000-0OHM,195-2655-000; CDS_SEC: 1; DEVICE_TYPENAME: R_0402-0OHM005OHM625MW195-2655-000-0OHM195-2655-000; DRAWING: @P2597_C02_LIB.P2597_C02(SCH_1):PAGE13; MAX_WATTAGE: 62.5mW; NV_PN: 195-2655-000; PATH: I330; PHYS_PAGE: 13; PLACEMENT_NOTE: CoLayout with L3; ROT: 0; SEC: 1; SIGNAL_MODEL: DEFAULT_RESISTOR_0.001OHM_2_1; TOL: 0.05 ohm; VER: 1; XY: (-3650,4350)
R24 = R: ASSEMBLY: ETHERNET; CDS_LIB: discrete; CDS_PART_NAME: R_0402-0OHM,0.05 OHM,62.5MW,195-2655-000; CDS_PHYS_PART_NAME: R_0402-0OHM,0.05 OHM,62.5MW,195-2655-000-0OHM,195-2655-000; CDS_SEC: 1; DEVICE_TYPENAME: R_0402-0OHM005OHM625MW195-2655-000-0OHM195-2655-000; DRAWING: @P2597_C02_LIB.P2597_C02(SCH_1):PAGE13; MAX_WATTAGE: 62.5mW; NV_PN: 195-2655-000; PATH: I328; PHYS_PAGE: 13; PLACEMENT_NOTE: CoLayout with L3; ROT: 0; SEC: 1; SIGNAL_MODEL: DEFAULT_RESISTOR_0.001OHM_2_1; TOL: 0.05 ohm; VER: 1; XY: (-3650,4050)
R25 = R: ASSEMBLY: ETHERNET; CDS_LIB: discrete; CDS_PART_NAME: R_0402-0OHM,0.05 OHM,62.5MW,195-2655-000; CDS_PHYS_PART_NAME: R_0402-0OHM,0.05 OHM,62.5MW,195-2655-000-0OHM,195-2655-000; CDS_SEC: 1; DEVICE_TYPENAME: R_0402-0OHM005OHM625MW195-2655-000-0OHM195-2655-000; DRAWING: @P2597_C02_LIB.P2597_C02(SCH_1):PAGE13; MAX_WATTAGE: 62.5mW; NV_PN: 195-2655-000; PATH: I327; PHYS_PAGE: 13; PLACEMENT_NOTE: CoLayout with L4; ROT: 0; SEC: 1; SIGNAL_MODEL: nv_res; TOL: 0.05 ohm; VER: 1; XY: (-3650,3900)
R30 = R: ASSEMBLY: ETHERNET; CDS_LIB: discrete; CDS_PART_NAME: R_0402-0OHM,0.05 OHM,62.5MW,195-2655-000; CDS_PHYS_PART_NAME: R_0402-0OHM,0.05 OHM,62.5MW,195-2655-000-0OHM,195-2655-000; CDS_SEC: 1; DEVICE_TYPENAME: R_0402-0OHM005OHM625MW195-2655-000-0OHM195-2655-000; DRAWING: @P2597_C02_LIB.P2597_C02(SCH_1):PAGE13; MAX_WATTAGE: 62.5mW; NV_PN: 195-2655-000; PATH: I325; PHYS_PAGE: 13; PLACEMENT_NOTE: CoLayout with L4; ROT: 0; SEC: 1; SIGNAL_MODEL: nv_res; TOL: 0.05 ohm; VER: 1; XY: (-3650,3600)
R31 = R: ASSEMBLY: ETHERNET; CDS_LIB: discrete; CDS_PART_NAME: R_0402-0OHM,0.05 OHM,62.5MW,195-2655-000; CDS_PHYS_PART_NAME: R_0402-0OHM,0.05 OHM,62.5MW,195-2655-000-0OHM,195-2655-000; CDS_SEC: 1; DEVICE_TYPENAME: R_0402-0OHM005OHM625MW195-2655-000-0OHM195-2655-000; DRAWING: @P2597_C02_LIB.P2597_C02(SCH_1):PAGE13; MAX_WATTAGE: 62.5mW; NV_PN: 195-2655-000; PATH: I324; PHYS_PAGE: 13; PLACEMENT_NOTE: CoLayout with L5; ROT: 0; SEC: 1; SIGNAL_MODEL: nv_res; TOL: 0.05 ohm; VER: 1; XY: (-3650,3450)
R35 = R: ASSEMBLY: ETHERNET; CDS_LIB: discrete; CDS_PART_NAME: R_0402-0OHM,0.05 OHM,62.5MW,195-2655-000; CDS_PHYS_PART_NAME: R_0402-0OHM,0.05 OHM,62.5MW,195-2655-000-0OHM,195-2655-000; CDS_SEC: 1; DEVICE_TYPENAME: R_0402-0OHM005OHM625MW195-2655-000-0OHM195-2655-000; DRAWING: @P2597_C02_LIB.P2597_C02(SCH_1):PAGE13; MAX_WATTAGE: 62.5mW; NV_PN: 195-2655-000; PATH: I322; PHYS_PAGE: 13; PLACEMENT_NOTE: CoLayout with L5; ROT: 0; SEC: 1; SIGNAL_MODEL: nv_res; TOL: 0.05 ohm; VER: 1; XY: (-3650,3150)
R40 = R: ASSEMBLY: ETHERNET; CDS_LIB: discrete; CDS_PART_NAME: R_0402-0OHM,0.05 OHM,62.5MW,195-2655-000; CDS_PHYS_PART_NAME: R_0402-0OHM,0.05 OHM,62.5MW,195-2655-000-0OHM,195-2655-000; CDS_SEC: 1; DEVICE_TYPENAME: R_0402-0OHM005OHM625MW195-2655-000-0OHM195-2655-000; DRAWING: @P2597_C02_LIB.P2597_C02(SCH_1):PAGE13; MAX_WATTAGE: 62.5mW; NV_PN: 195-2655-000; PATH: I394; PHYS_PAGE: 13; ROT: 0; SEC: 1; SIGNAL_MODEL: nv_res; SKU: NO STUFF; TOL: 0.05 ohm; VER: 1; XY: (-1350,2600)
R44 = R: ASSEMBLY: ETHERNET; CDS_LIB: discrete; CDS_PART_NAME: R_0402-681OHM,1 %,62.5MW,195-0403-000; CDS_PHYS_PART_NAME: R_0402-681OHM,1 %,62.5MW,195-0403-000-195-0403-000,681OHM; CDS_SEC: 1; DEVICE_TYPENAME: R_0402-681OHM1625MW195-0403-000-195-0403-000681OHM; DRAWING: @P2597_C02_LIB.P2597_C02(SCH_1):PAGE13; MAX_WATTAGE: 62.5mW; NV_PN: 195-0403-000; PATH: I321; PHYS_PAGE: 13; ROT: 0; SEC: 1; SIGNAL_MODEL: DEFAULT_RESISTOR_510OHM_2_1; TOL: 1%; VER: 1; XY: (-3000,2600)
R45 = R: ASSEMBLY: ETHERNET; CDS_LIB: discrete; CDS_PART_NAME: R_0402-0OHM,0.05 OHM,62.5MW,195-2655-000; CDS_PHYS_PART_NAME: R_0402-0OHM,0.05 OHM,62.5MW,195-2655-000-0OHM,195-2655-000; CDS_SEC: 1; DEVICE_TYPENAME: R_0402-0OHM005OHM625MW195-2655-000-0OHM195-2655-000; DRAWING: @P2597_C02_LIB.P2597_C02(SCH_1):PAGE13; MAX_WATTAGE: 62.5mW; NV_PN: 195-2655-000; PATH: I393; PHYS_PAGE: 13; ROT: 0; SEC: 1; SIGNAL_MODEL: nv_res; SKU: NO STUFF; TOL: 0.05 ohm; VER: 1; XY: (-1350,3100)
R46 = R: ASSEMBLY: ETHERNET; CDS_LIB: discrete; CDS_PART_NAME: R_0603-0OHM,0.05 OHM,0.1W,195-2656-000; CDS_PHYS_PART_NAME: R_0603-0OHM,0.05 OHM,0.1W,195-2656-000-0OHM,195-2656-000; CDS_SEC: 1; DEVICE_TYPENAME: R_0603-0OHM005OHM01W195-2656-000-0OHM195-2656-000; DRAWING: @P2597_C02_LIB.P2597_C02(SCH_1):PAGE13; MAX_WATTAGE: 0.1W; NV_PN: 195-2656-000; PATH: I344; PHYS_PAGE: 13; ROT: 0; SEC: 1; SIGNAL_MODEL: DEFAULT_RESISTOR_0.001OHM_2_1; SKU: NO STUFF; TOL: 0.05 ohm; VER: 1; XY: (-1350,2350)
R47 = R: ASSEMBLY: ETHERNET; CDS_LIB: discrete; CDS_PART_NAME: R_0603-0OHM,0.05 OHM,0.1W,195-2656-000; CDS_PHYS_PART_NAME: R_0603-0OHM,0.05 OHM,0.1W,195-2656-000-0OHM,195-2656-000; CDS_SEC: 1; DEVICE_TYPENAME: R_0603-0OHM005OHM01W195-2656-000-0OHM195-2656-000; DRAWING: @P2597_C02_LIB.P2597_C02(SCH_1):PAGE13; MAX_WATTAGE: 0.1W; NV_PN: 195-2656-000; PATH: I343; PHYS_PAGE: 13; ROT: 0; SEC: 1; SIGNAL_MODEL: DEFAULT_RESISTOR_0.001OHM_2_1; SKU: NO STUFF; TOL: 0.05 ohm; VER: 1; XY: (-1350,2250)
R597 = R: ASSEMBLY: ETHERNET; CDS_LIB: discrete; CDS_PART_NAME: R_0402-75OHM,5 %,62.5MW,195-0631-000; CDS_PHYS_PART_NAME: R_0402-75OHM,5 %,62.5MW,195-0631-000-195-0631-000,75OHM; CDS_SEC: 1; DEVICE_TYPENAME: R_0402-75OHM5625MW195-0631-000-195-0631-00075OHM; DRAWING: @P2597_C02_LIB.P2597_C02(SCH_1):PAGE13; MAX_WATTAGE: 62.5mW; NV_PN: 195-0631-000; PATH: I294; PHYS_PAGE: 13; ROT: 0; SEC: 1; SIGNAL_MODEL: nv_res; TOL: 5%; VER: 1; XY: (-5800,3750)
R598 = R: ASSEMBLY: ETHERNET; CDS_LIB: discrete; CDS_PART_NAME: R_0402-75OHM,5 %,62.5MW,195-0631-000; CDS_PHYS_PART_NAME: R_0402-75OHM,5 %,62.5MW,195-0631-000-195-0631-000,75OHM; CDS_SEC: 1; DEVICE_TYPENAME: R_0402-75OHM5625MW195-0631-000-195-0631-00075OHM; DRAWING: @P2597_C02_LIB.P2597_C02(SCH_1):PAGE13; MAX_WATTAGE: 62.5mW; NV_PN: 195-0631-000; PATH: I295; PHYS_PAGE: 13; ROT: 0; SEC: 1; SIGNAL_MODEL: nv_res; TOL: 5%; VER: 1; XY: (-5800,3900)
R599 = R: ASSEMBLY: ETHERNET; CDS_LIB: discrete; CDS_PART_NAME: R_0402-75OHM,5 %,62.5MW,195-0631-000; CDS_PHYS_PART_NAME: R_0402-75OHM,5 %,62.5MW,195-0631-000-195-0631-000,75OHM; CDS_SEC: 1; DEVICE_TYPENAME: R_0402-75OHM5625MW195-0631-000-195-0631-00075OHM; DRAWING: @P2597_C02_LIB.P2597_C02(SCH_1):PAGE13; MAX_WATTAGE: 62.5mW; NV_PN: 195-0631-000; PATH: I296; PHYS_PAGE: 13; ROT: 0; SEC: 1; SIGNAL_MODEL: DEFAULT_RESISTOR_75OHM_2_1; TOL: 5%; VER: 1; XY: (-5800,4050)
R600 = R: ASSEMBLY: ETHERNET; CDS_LIB: discrete; CDS_PART_NAME: R_0402-75OHM,5 %,62.5MW,195-0631-000; CDS_PHYS_PART_NAME: R_0402-75OHM,5 %,62.5MW,195-0631-000-195-0631-000,75OHM; CDS_SEC: 1; DEVICE_TYPENAME: R_0402-75OHM5625MW195-0631-000-195-0631-00075OHM; DRAWING: @P2597_C02_LIB.P2597_C02(SCH_1):PAGE13; MAX_WATTAGE: 62.5mW; NV_PN: 195-0631-000; PATH: I297; PHYS_PAGE: 13; ROT: 0; SEC: 1; SIGNAL_MODEL: DEFAULT_RESISTOR_75OHM_2_1; TOL: 5%; VER: 1; XY: (-5800,4200)
T1 = TR_ENET_MAGCOM: ASSEMBLY: ETHERNET; CDS_LIB: discrete; CDS_PART_NAME: TR_ENET_MAGCOM_SOP24-M3295NL,1:1,1500V(RMS),0HZ..100MHZ,50OHM..50OHM,295-0036-000; CDS_PHYS_PART_NAME: TR_ENET_MAGCOM_SOP24-M3295NL,1:1,1500V(RMS),0HZ..100MHZ,50OHM..50OHM,295-0036-000-1:1,295-0036-000; CDS_SEC: 1; DEVICE_TYPENAME: TR_ENET_MAGCOM_SOP24-M3295NL111500VRMS0HZ100MHZ50OHM50OHM295-0036-000-11295-0036-000; DRAWING: @P2597_C02_LIB.P2597_C02(SCH_1):PAGE13; FREQ_RANGE: 0Hz..100MHz; IMPEDANCE: 50ohm..50ohm; ISOLATING_VOLTAGE: 1500V(rms); NV_NAME: M3295NL; NV_PN: 295-0036-000; PACK_TYPE: SOP24; PATH: I377; PHYS_PAGE: 13; ROT: 0; SEC: 1; SEC_TYPE: SOP24; VER: 2; XY: (-7500,4000)

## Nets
GND: C10.2 C25.2 C26.2 C31.2 C39.2 C197.2 C198.2 C199.2 C205.1 D506.2(GND1) D507.2(GND1) J1.1(SH) J1.2(SH) J1.P4(GND_4) J1.P5(GND_5) J1.P6(GND_6) J1.P10(GND_7) J1.P12(GND_8) J1.S1(GND_1) J1.S4(GND_2) J1.S7(GND_3) Q2.2(S) Q34.2(S) Q35.2(S) R8.1 R12.1 R40.1 R45.1 R46.1 R47.1 R346.2 U1.3(GND) ; also on sheet 1 2 3 4 5 6 7 9 10 11 12 13 14 15 16 17 18 19 20 23 24 25 26 30
VDD_1V8: C10.1 R314.1 U1.5(VCC) ; also on sheet 4 5 9 10 12 13 16 17 18 19 20 24 30
VDD_3V3_SLP: C26.1 D506.5(PWR1) D507.5(PWR1) J5.10 J5.12 Q2.1(G) R315.1 ; also on sheet 4 5 11 16 17 20 25
VDD_5V0_IO_SLP: C28.2 J1.P7(5V_1) J1.P8(5V_2) J1.P9(5V_3) Q1.5(D) R308.1 ; also on sheet 12
VDD_5V0_IO_SLP_DISCHARGE: Q34.3(D) R308.2
VDD_5V0_IO_SYS: Q1.1(S1) Q1.2(S2) Q1.3(S3) R11.1 ; also on sheet 4 5 6 9 11 12 16 17 18 20 26 30
VDD_12V_SLP: J1.P13(12V_1) J1.P14(12V_2) J1.P15(12V_3) R309.1 R347.1 ; also on sheet 11 12 25
VDD_12V_SLP_DISCHARGE: Q35.3(D) R309.2 R347.2
CGND: C27.2 C205.2 J5.13 J5.14 R8.2 R12.2 R40.2 R45.2 R46.2 R47.2
DISCHARGE: D18.1(A1) R348.2 ; also on sheet 4
EN_VDD_SATA_G: C28.1 Q1.4(G) R11.2 R13.1
EN_VDD_SATA_R_D_L: D18.3(CC) Q34.1(G) Q35.1(G) R346.1 R348.1
EN_VDD_SATA_R_L: D18.2(A2) Q2.3(D) R13.2
GBE_LED0_SPICSB: R10.1 ; also on sheet 28
GBE_LED1_SPISCK: R44.1 ; also on sheet 28
GBE_MDI0_N: D507.1 T1.3(TD1N) ; also on sheet 28
GBE_MDI0_P: D507.6 T1.2(TD1P) ; also on sheet 28
GBE_MDI1_N: D507.4 T1.6(TD2N) ; also on sheet 28
GBE_MDI1_P: D507.3 T1.5(TD2P) ; also on sheet 28
GBE_MDI2_N: D506.1 T1.9(TD3N) ; also on sheet 28
GBE_MDI2_P: D506.6 T1.8(TD3P) ; also on sheet 28
GBE_MDI3_N: D506.4 T1.12(TD4N) ; also on sheet 28
GBE_MDI3_P: D506.3 T1.11(TD4P) ; also on sheet 28
MCT0: R600.1 T1.24(MCT1)
MCT1: R599.1 T1.21(MCT2)
MCT2: R598.1 T1.18(MCT3)
MCT3: R597.1 T1.15(MCT4)
MDI_CT0: C198.1 T1.1(TCT1)
MDI_CT1: C31.1 T1.4(TCT2)
MDI_CT2: C199.1 T1.7(TCT3)
MDI_CT3: C197.1 T1.10(TCT4)
RJ45_RDN: L3.2 R24.1 T1.19(MX2N)
RJ45_RDN1: L5.2 R35.1 T1.13(MX4N)
RJ45_RDN1_F: J5.8 L5.3 R35.2
RJ45_RDN_F: J5.6 L3.3 R24.2
RJ45_RDP: L3.1 R23.1 T1.20(MX2P)
RJ45_RDP1: L5.1 R31.1 T1.14(MX4P)
RJ45_RDP1_F: J5.7 L5.4 R31.2
RJ45_RDP_F: J5.3 L3.4 R23.2
RJ45_TDN: L1.2 R21.1 T1.22(MX1N)
RJ45_TDN1: L4.2 R30.1 T1.16(MX3N)
RJ45_TDN1_F: J5.5 L4.3 R30.2
RJ45_TDN_F: J5.2 L1.3 R21.2
RJ45_TDP: L1.1 R18.1 T1.23(MX1P)
RJ45_TDP1: L4.1 R25.1 T1.17(MX3P)
RJ45_TDP1_F: J5.4 L4.4 R25.2
RJ45_TDP_F: J5.1 L1.4 R18.2
RJ_CAP: C27.1 R597.2 R598.2 R599.2 R600.2
RJ_LED1: C25.1 J5.9 R10.2
RJ_LED2: C39.1 J5.11 R44.2
SATA_DEV_SLP: R314.2 U1.2(A) ; also on sheet 28
SATA_DEV_SLP_3V3: J1.P3(3V3_3) R315.2 U1.4(Y)
SATA_RX_C_N: C7.2 J1.S5(B*)
SATA_RX_C_P: C8.2 J1.S6(B)
SATA_RX_N: C7.1 ; also on sheet 28
SATA_RX_P: C8.1 ; also on sheet 28
SATA_TX_C_N: C6.2 J1.S3(A*)
SATA_TX_C_P: C5.2 J1.S2(A)
SATA_TX_N: C6.1 ; also on sheet 28
SATA_TX_P: C5.1 ; also on sheet 28
SNN_SATA_P1: J1.P1(3V3_1)
SNN_SATA_P2: J1.P2(3V3_2)
SNN_SATA_P11: J1.P11(DAS_11)

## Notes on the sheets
sheet 21
- A
- B
- C
- D
- E
- F
- G
- H
- Gigiabit Ethernet
- 1
- 1
- 2
- 2
- PCB CO-LAYOUT
- 3
- 3
- Sprinkle around CGND shape
- 4
- 4
- 5
- 5
- NVIDIA CORPORATION
- 2701 SAN TOMAS EXPRESSWAY
- ASSEMBLY
- <ASSEMBLY_DESCRIPTION>
- SANTA CLARA, CA 95050, USA
- PAGE DETAIL
- Gigabit Ethernet
- NV_PN
- 600-82597-BASE-900
- ALL NVIDIA DESIGN SPECIFICATIONS, REFERENCE SPECIFICATIONS, REFERENCE BOARDS, FILES, DRAWINGS, DIAGNOSTICS, LISTS AND OTHER DOCUMENTS OR INFORMATION (TOGETHER AND SEPARATELY, 'MATERIALS') ARE BEING PROVIDED 'AS IS'. THE MATERIALS MAY
- CONTAIN KNOWN AND UNKNOWN VIOLATIONS OR DEVIATIONS OF INDUSTRY STANDARDS AND SPECIFICATIONS. NVIDIA MAKES NO WARRANTIES, EXPRESSED, IMPLIED, STATUTORY OR OTHERWISE WITH RESPECT TO THE MATERIALS OR OTHERWISE, AND EXPRESSLY DISCLAIMS ALL
- PCB REV
- P2597-C02
- PAGE
- 13 OF 34
- IMPLIED WARRANTIES INCLUDING, WITHOUT LIMITATION, THE WARRANTIES OF DESIGN, OF NONINFRINGEMENT, MERCHANTABILITY OR FITNESS FOR A PARTICULAR PURPOSE, OR ARISING FROM A COURSE OF DEALING, TRADE USAGE, TRADE PRACTICE, OR INDUSTRY STANDARDS.
- BOM REV
- A
- DATE
- 23-OCT-2017
- A
- B
- C
- D
- E
- F
- G
- H
sheet 22
- A
- B
- C
- D
- E
- F
- G
- H
- SATA Connector
- 1
- 1
- 2
- 2
- NS
- 3
- 3
- 4
- 4
- NS
- NS
- 5
- 5
- NVIDIA CORPORATION
- 2701 SAN TOMAS EXPRESSWAY
- ASSEMBLY
- <ASSEMBLY_DESCRIPTION>
- SANTA CLARA, CA 95050, USA
- PAGE DETAIL
- SATA
- NV_PN
- 600-82597-BASE-900
- ALL NVIDIA DESIGN SPECIFICATIONS, REFERENCE SPECIFICATIONS, REFERENCE BOARDS, FILES, DRAWINGS, DIAGNOSTICS, LISTS AND OTHER DOCUMENTS OR INFORMATION (TOGETHER AND SEPARATELY, 'MATERIALS') ARE BEING PROVIDED 'AS IS'. THE MATERIALS MAY
- CONTAIN KNOWN AND UNKNOWN VIOLATIONS OR DEVIATIONS OF INDUSTRY STANDARDS AND SPECIFICATIONS. NVIDIA MAKES NO WARRANTIES, EXPRESSED, IMPLIED, STATUTORY OR OTHERWISE WITH RESPECT TO THE MATERIALS OR OTHERWISE, AND EXPRESSLY DISCLAIMS ALL
- PCB REV
- P2597-C02
- PAGE
- 12 OF 34
- IMPLIED WARRANTIES INCLUDING, WITHOUT LIMITATION, THE WARRANTIES OF DESIGN, OF NONINFRINGEMENT, MERCHANTABILITY OR FITNESS FOR A PARTICULAR PURPOSE, OR ARISING FROM A COURSE OF DEALING, TRADE USAGE, TRADE PRACTICE, OR INDUSTRY STANDARDS.
- BOM REV
- A
- DATE
- 23-OCT-2017
- A
- B
- C
- D
- E
- F
- G
- H
